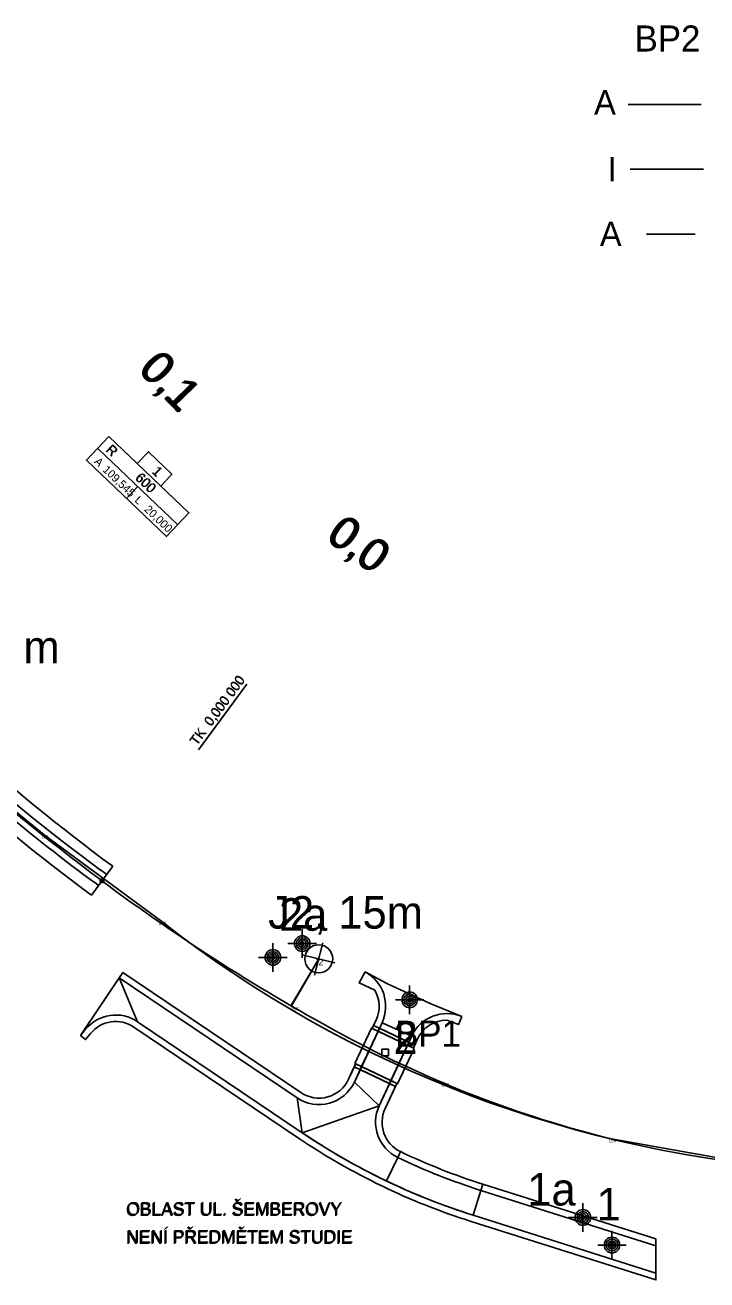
# Model space of a CAD drawing. Extents: x -606444 to -604546, y -1158114 to -1156869.
# Drawn here: x -604958.2 to -604748.6, y -1157651 to -1157265.4 of the extents above; entities that cross this region are included whole.
import ezdxf

# ---------------------------------------------------------------- set-up
doc = ezdxf.new("R2010")
doc.units = 0
for name, color, linetype in [('0_sondy', 7, 'Continuous'), ('B_CHOD', 7, 'Continuous'), ('B_TRAM', 7, 'Continuous'), ('B_VOZ', 7, 'Continuous'), ('jádrové vrty_předběžný GTP', 7, 'Continuous'), ('korozní průzkum', 7, 'Continuous'), ('legenda', 7, 'Continuous'), ('netisk', 7, 'Continuous'), ('netisk2', 7, 'Continuous'), ('NS_VB', 7, 'Continuous'), ('NS_VB_POP', 7, 'Continuous'), ('OSA', 7, 'Continuous'), ('OSAPOP', 7, 'Continuous'), ('podélný profil trasou tramvaje', 7, 'Continuous'), ('Sondy 2', 7, 'Continuous'), ('sondy současného průzkumu', 7, 'Continuous')]:
    doc.layers.add(name, color=color, linetype=linetype)

# ---------------------------------------------------------------- blocks, each defined once
blk = doc.blocks.new('709')
for p, q in [((0, 2.2), (0, -2.2)), ((-2.2, 0), (2.2, 0))]:
    blk.add_line(p, q)
for radius in [1.2, 0.9, 0.6, 0.3]:
    blk.add_circle((0, 0), radius)
blk = doc.blocks.new('IG vrt podr')
at = {"layer": 'sondy současného průzkumu'}
for p, q in [((0.41, 1.65), (-0.42, -1.67)), ((-1.7, 0.42), (1.64, -0.41))]:
    blk.add_line(p, q, dxfattribs=at)
blk.add_circle((0, 0), 1.43, dxfattribs=at)

msp = doc.modelspace()

# ---------------------------------------------------------------- linework, layer by layer
for p, q in [((-604952.36, -1157514.24), (-604952.46, -1157514.14)), ((-604952.36, -1157514.24), (-604952.46, -1157514.34)), ((-604952.36, -1157514.24), (-604952.26, -1157514.14)), ((-604952.36, -1157514.24), (-604952.26, -1157514.34)), ((-604916.22, -1157540.87), (-604916.32, -1157540.77)), ((-604916.22, -1157540.87), (-604916.32, -1157540.97)), ((-604916.22, -1157540.87), (-604916.12, -1157540.77)), ((-604916.22, -1157540.87), (-604916.12, -1157540.97)), ((-604867.95, -1157552.31), (-604868.05, -1157552.21)), ((-604867.95, -1157552.31), (-604868.05, -1157552.41)), ((-604867.95, -1157552.31), (-604867.85, -1157552.21)), ((-604867.95, -1157552.31), (-604867.85, -1157552.41)), ((-604875.6, -1157567.24), (-604875.7, -1157567.14)), ((-604875.6, -1157567.24), (-604875.7, -1157567.34)), ((-604875.6, -1157567.24), (-604875.5, -1157567.14)), ((-604875.6, -1157567.24), (-604875.5, -1157567.34)), ((-604829.38, -1157590.46), (-604829.48, -1157590.36)), ((-604829.38, -1157590.46), (-604829.48, -1157590.56)), ((-604829.38, -1157590.46), (-604829.28, -1157590.36)), ((-604829.38, -1157590.46), (-604829.28, -1157590.56)), ((-604777.97, -1157607.68), (-604778.07, -1157607.58)), ((-604777.97, -1157607.68), (-604778.07, -1157607.78)), ((-604777.97, -1157607.68), (-604777.87, -1157607.58)), ((-604777.97, -1157607.68), (-604777.87, -1157607.78))]:
    msp.add_line(p, q)
at = {"layer": 'B_CHOD'}
for p, q in [((-604818.1, -1157623.48), (-604817.49, -1157621.57)), ((-604818.1, -1157623.48), (-604817.49, -1157621.57)), ((-604817.49, -1157621.57), (-604764.31, -1157638.39)), ((-604817.49, -1157621.57), (-604764.31, -1157638.39)), ((-604764.31, -1157640.49), (-604818.1, -1157623.48)), ((-604764.31, -1157640.49), (-604818.1, -1157623.48)), ((-604764.31, -1157638.39), (-604764.31, -1157640.49)), ((-604764.31, -1157638.39), (-604764.31, -1157640.49))]:
    msp.add_line(p, q, dxfattribs=at)
for points in [[(-604873.47, -1157593.4), (-604928.14, -1157556.52), (-604929.26, -1157558.18), (-604874.59, -1157595.05)], [(-604873.47, -1157593.4), (-604928.14, -1157556.52), (-604929.26, -1157558.18), (-604874.59, -1157595.05)], [(-604853.73, -1157556.29), (-604855.56, -1157559.72), (-604850.68, -1157561.94)], [(-604853.73, -1157556.29), (-604855.56, -1157559.72), (-604850.68, -1157561.94)], [(-604873.06, -1157605.73), (-604923.64, -1157571.62)], [(-604873.06, -1157605.73), (-604923.64, -1157571.62)], [(-604851.11, -1157572.8), (-604851.53, -1157573.7), (-604849.72, -1157574.56), (-604849.3, -1157573.66), (-604851.11, -1157572.8)], [(-604851.11, -1157572.8), (-604851.53, -1157573.7), (-604849.72, -1157574.56), (-604849.3, -1157573.66), (-604851.11, -1157572.8)], [(-604850.31, -1157571.1), (-604851.11, -1157572.8), (-604849.3, -1157573.66), (-604848.5, -1157571.95)], [(-604850.31, -1157571.1), (-604851.11, -1157572.8), (-604849.3, -1157573.66), (-604848.5, -1157571.95)], [(-604828.56, -1157571.11), (-604825.03, -1157572.52), (-604824.01, -1157569.98)], [(-604828.56, -1157571.11), (-604825.03, -1157572.52), (-604824.01, -1157569.98)], [(-604939.63, -1157573.96), (-604941.17, -1157575.84), (-604939.62, -1157577.11), (-604938.08, -1157575.23)], [(-604939.63, -1157573.96), (-604941.17, -1157575.84), (-604939.62, -1157577.11), (-604938.08, -1157575.23)], [(-604924.76, -1157573.28), (-604874.18, -1157607.39)], [(-604924.76, -1157573.28), (-604874.18, -1157607.39)], [(-604856.82, -1157584.47), (-604856.6, -1157584.58), (-604854.79, -1157585.44), (-604849.72, -1157574.56), (-604851.53, -1157573.7), (-604851.75, -1157573.6), (-604856.82, -1157584.47)], [(-604856.82, -1157584.47), (-604856.6, -1157584.58), (-604854.79, -1157585.44), (-604849.72, -1157574.56), (-604851.53, -1157573.7), (-604851.75, -1157573.6), (-604856.82, -1157584.47)], [(-604839.38, -1157576.04), (-604840.26, -1157577.94), (-604838.45, -1157578.8), (-604837.56, -1157576.88)], [(-604839.38, -1157576.04), (-604840.26, -1157577.94), (-604838.45, -1157578.8), (-604837.56, -1157576.88)], [(-604838.65, -1157579.81), (-604838.88, -1157579.7), (-604840.68, -1157578.85), (-604845.76, -1157589.72), (-604843.95, -1157590.58), (-604843.72, -1157590.69), (-604838.65, -1157579.81)], [(-604838.65, -1157579.81), (-604838.88, -1157579.7), (-604840.68, -1157578.85), (-604845.76, -1157589.72), (-604843.95, -1157590.58), (-604843.72, -1157590.69), (-604838.65, -1157579.81)], [(-604838.88, -1157579.7), (-604838.45, -1157578.8), (-604840.26, -1157577.94), (-604840.68, -1157578.85), (-604838.88, -1157579.7)], [(-604838.88, -1157579.7), (-604838.45, -1157578.8), (-604840.26, -1157577.94), (-604840.68, -1157578.85), (-604838.88, -1157579.7)], [(-604856.6, -1157584.58), (-604857.02, -1157585.49), (-604855.21, -1157586.34), (-604854.79, -1157585.44), (-604856.6, -1157584.58)], [(-604856.6, -1157584.58), (-604857.02, -1157585.49), (-604855.21, -1157586.34), (-604854.79, -1157585.44), (-604856.6, -1157584.58)], [(-604857, -1157590.18), (-604855.21, -1157586.34), (-604857.02, -1157585.49), (-604858.81, -1157589.33)], [(-604857, -1157590.18), (-604855.21, -1157586.34), (-604857.02, -1157585.49), (-604858.81, -1157589.33)], [(-604847.56, -1157598.32), (-604844.37, -1157591.49), (-604846.18, -1157590.63), (-604849.37, -1157597.47)], [(-604847.56, -1157598.32), (-604844.37, -1157591.49), (-604846.18, -1157590.63), (-604849.37, -1157597.47)], [(-604844.37, -1157591.49), (-604843.95, -1157590.58), (-604845.76, -1157589.72), (-604846.18, -1157590.63), (-604844.37, -1157591.49)], [(-604844.37, -1157591.49), (-604843.95, -1157590.58), (-604845.76, -1157589.72), (-604846.18, -1157590.63), (-604844.37, -1157591.49)], [(-604843.68, -1157613.36), (-604843.68, -1157613.36), (-604842.81, -1157611.56)], [(-604842.81, -1157611.56), (-604842.81, -1157611.56), (-604843.68, -1157613.36)], [(-604843.68, -1157613.36), (-604843.68, -1157613.36), (-604842.81, -1157611.56)], [(-604842.81, -1157611.56), (-604842.81, -1157611.56), (-604843.68, -1157613.36)], [(-604818.1, -1157623.48), (-604817.49, -1157621.57)], [(-604818.1, -1157623.48), (-604817.49, -1157621.57)], [(-604821.11, -1157633.01), (-604764.31, -1157650.98), (-604764.31, -1157648.88), (-604820.51, -1157631.11)], [(-604821.11, -1157633.01), (-604764.31, -1157650.98), (-604764.31, -1157648.88), (-604820.51, -1157631.11)]]:
    msp.add_lwpolyline(points, dxfattribs=at)
for centre, radius, start, end in [((-604859.38, -1157566.88), 12, 335.0043, 61.9243), ((-604859.38, -1157566.88), 12, 335.0043, 61.9243), ((-604859.38, -1157566.88), 10, 335.0043, 29.5887), ((-604859.38, -1157566.88), 10, 335.0043, 29.5887), ((-604828.5, -1157581.11), 12, 68.0258, 155.0043), ((-604828.5, -1157581.11), 12, 68.0258, 155.0043), ((-604930.35, -1157581.57), 12, 56.0043, 140.6259), ((-604930.35, -1157581.57), 12, 56.0043, 140.6259), ((-604930.35, -1157581.57), 10, 56.0043, 140.6259), ((-604930.35, -1157581.57), 10, 56.0043, 140.6259), ((-604828.5, -1157581.11), 10, 90.366, 155.0043), ((-604828.5, -1157581.11), 10, 90.366, 155.0043), ((-604867.88, -1157585.11), 12, 236.0043, 335.0043), ((-604867.88, -1157585.11), 12, 236.0043, 335.0043), ((-604867.88, -1157585.11), 10, 236.0043, 335.0043), ((-604867.88, -1157585.11), 10, 236.0043, 335.0043), ((-604838.49, -1157602.54), 12, 155.0043, 244.4037), ((-604838.49, -1157602.54), 12, 155.0043, 244.4037), ((-604838.49, -1157602.54), 10, 155.0043, 244.404), ((-604838.49, -1157602.54), 10, 155.0043, 244.404), ((-604759, -1157436.6), 206, 236.0043, 252.4517), ((-604759, -1157436.6), 206, 236.0043, 252.4517), ((-604759, -1157436.6), 204, 236.0043, 252.4517), ((-604759, -1157436.6), 204, 236.0043, 252.4517), ((-604759, -1157436.6), 194, 244.404, 252.4516), ((-604759, -1157436.6), 194, 244.404, 252.4516), ((-604759, -1157436.6), 196, 244.404, 252.4516), ((-604759, -1157436.6), 196, 244.404, 252.4516)]:
    msp.add_arc(centre, radius, start, end, dxfattribs=at)
at = {"layer": 'B_TRAM'}
msp.add_line((-604937.81, -1157532.72), (-604931.28, -1157523.87), dxfattribs=at)
for radius in [594.5, 605.5]:
    msp.add_arc((-604578.51, -1157045.35), radius, 222.04255, 233.60158, dxfattribs=at)
at = {"layer": 'B_VOZ'}
for p, q in [((-604929.26, -1157558.18), (-604941.17, -1157575.84)), ((-604929.26, -1157558.18), (-604941.17, -1157575.84)), ((-604923.64, -1157571.62), (-604929.26, -1157558.18)), ((-604923.64, -1157571.62), (-604929.26, -1157558.18)), ((-604941.17, -1157575.84), (-604939.63, -1157573.96)), ((-604941.17, -1157575.84), (-604939.63, -1157573.96))]:
    msp.add_line(p, q, dxfattribs=at)
for points in [[(-604824.01, -1157569.98), (-604833.75, -1157566.05), (-604847.07, -1157559.84), (-604853.73, -1157556.29)], [(-604824.01, -1157569.98), (-604833.75, -1157566.05), (-604847.07, -1157559.84), (-604853.73, -1157556.29)], [(-604923.64, -1157571.62), (-604873.06, -1157605.73), (-604874.59, -1157595.05), (-604929.26, -1157558.18), (-604923.64, -1157571.62)], [(-604923.64, -1157571.62), (-604873.06, -1157605.73), (-604874.59, -1157595.05), (-604929.26, -1157558.18), (-604923.64, -1157571.62)], [(-604840.26, -1157577.94), (-604839.38, -1157576.04), (-604848.5, -1157571.95), (-604849.3, -1157573.66), (-604840.26, -1157577.94)], [(-604840.26, -1157577.94), (-604839.38, -1157576.04), (-604848.5, -1157571.95), (-604849.3, -1157573.66), (-604840.26, -1157577.94)], [(-604848.5, -1157571.95), (-604839.38, -1157576.04)], [(-604848.5, -1157571.95), (-604839.38, -1157576.04)], [(-604845.76, -1157589.72), (-604840.68, -1157578.85), (-604849.72, -1157574.56), (-604854.79, -1157585.44), (-604845.76, -1157589.72)], [(-604845.76, -1157589.72), (-604840.68, -1157578.85), (-604849.72, -1157574.56), (-604854.79, -1157585.44), (-604845.76, -1157589.72)], [(-604840.68, -1157578.85), (-604840.26, -1157577.94), (-604849.3, -1157573.66), (-604849.72, -1157574.56), (-604840.68, -1157578.85)], [(-604840.68, -1157578.85), (-604840.26, -1157577.94), (-604849.3, -1157573.66), (-604849.72, -1157574.56), (-604840.68, -1157578.85)], [(-604849.37, -1157597.47), (-604846.18, -1157590.63), (-604855.21, -1157586.34), (-604857, -1157590.18), (-604849.37, -1157597.47)], [(-604849.37, -1157597.47), (-604846.18, -1157590.63), (-604855.21, -1157586.34), (-604857, -1157590.18), (-604849.37, -1157597.47)], [(-604846.18, -1157590.63), (-604845.76, -1157589.72), (-604854.79, -1157585.44), (-604855.21, -1157586.34), (-604846.18, -1157590.63)], [(-604846.18, -1157590.63), (-604845.76, -1157589.72), (-604854.79, -1157585.44), (-604855.21, -1157586.34), (-604846.18, -1157590.63)], [(-604874.59, -1157595.05), (-604873.06, -1157605.73), (-604849.37, -1157597.47), (-604857, -1157590.18)], [(-604874.59, -1157595.05), (-604873.06, -1157605.73), (-604849.37, -1157597.47), (-604857, -1157590.18)], [(-604849.37, -1157597.47), (-604873.06, -1157605.73)], [(-604849.37, -1157597.47), (-604873.06, -1157605.73)], [(-604847.13, -1157620.58), (-604843.68, -1157613.36)], [(-604843.68, -1157613.36), (-604843.68, -1157613.36), (-604847.13, -1157620.58)], [(-604847.13, -1157620.58), (-604843.68, -1157613.36)], [(-604843.68, -1157613.36), (-604843.68, -1157613.36), (-604847.13, -1157620.58)], [(-604820.51, -1157631.11), (-604818.1, -1157623.48)], [(-604764.31, -1157640.49), (-604818.1, -1157623.48), (-604820.51, -1157631.11), (-604764.31, -1157648.88), (-604764.31, -1157640.49)], [(-604820.51, -1157631.11), (-604818.1, -1157623.48)], [(-604764.31, -1157640.49), (-604818.1, -1157623.48), (-604820.51, -1157631.11), (-604764.31, -1157648.88), (-604764.31, -1157640.49)]]:
    msp.add_lwpolyline(points, dxfattribs=at)
for centre, radius, start, end in [((-604859.38, -1157566.88), 12, 335.0043, 61.9245), ((-604859.38, -1157566.88), 12, 335.0043, 61.9245), ((-604828.5, -1157581.11), 12, 68.0258, 155.0043), ((-604828.5, -1157581.11), 12, 68.0258, 155.0043), ((-604930.35, -1157581.57), 12, 56.0043, 140.6259), ((-604930.35, -1157581.57), 12, 56.0043, 140.6259), ((-604867.88, -1157585.11), 12, 236.0043, 335.0043), ((-604867.88, -1157585.11), 12, 236.0043, 335.0043), ((-604838.49, -1157602.54), 12, 155.0043, 244.404), ((-604838.49, -1157602.54), 12, 155.0043, 244.404), ((-604759, -1157436.6), 204, 236.0043, 244.404), ((-604759, -1157436.6), 204, 236.0043, 244.404), ((-604759, -1157436.6), 196, 244.404, 252.4517), ((-604759, -1157436.6), 196, 244.404, 252.4517), ((-604759, -1157436.6), 204, 244.404, 252.4517), ((-604759, -1157436.6), 204, 244.404, 252.4517)]:
    msp.add_arc(centre, radius, start, end, dxfattribs=at)
at = {"layer": 'korozní průzkum'}
msp.add_lwpolyline([(-604848.6, -1157580.06), (-604846.52, -1157580.06), (-604846.52, -1157582.1), (-604848.6, -1157582.1)], close=True, dxfattribs=at)
at = {"layer": 'legenda'}
for p, q in [((-604772.89, -1157289.8), (-604750.39, -1157289.8)), ((-604772.22, -1157309.61), (-604749.72, -1157309.61))]:
    msp.add_line(p, q, dxfattribs=at)
at = {"layer": 'netisk'}
msp.add_line((-604876.35, -1157566.48), (-604867.95, -1157552.31), dxfattribs=at)
at = {"layer": 'netisk2'}
msp.add_line((-604867.95, -1157552.31), (-604876.34, -1157566.79), dxfattribs=at)
at = {"layer": 'NS_VB'}
for p, q in [((-604931.28, -1157523.87), (-604937.81, -1157532.72)), ((-604941.17, -1157575.84), (-604928.14, -1157556.52)), ((-604873.47, -1157593.4), (-604928.14, -1157556.52)), ((-604853.73, -1157556.29), (-604855.56, -1157559.72)), ((-604847.07, -1157559.84), (-604853.73, -1157556.29)), ((-604874.59, -1157595.05), (-604929.26, -1157558.18)), ((-604850.68, -1157561.94), (-604855.56, -1157559.72)), ((-604833.75, -1157566.05), (-604847.07, -1157559.84)), ((-604824.01, -1157569.98), (-604833.75, -1157566.05)), ((-604873.06, -1157605.73), (-604923.64, -1157571.62)), ((-604848.5, -1157571.95), (-604857, -1157590.18)), ((-604850.31, -1157571.1), (-604851.53, -1157573.7)), ((-604838.45, -1157578.8), (-604851.11, -1157572.8)), ((-604828.56, -1157571.11), (-604825.03, -1157572.52)), ((-604825.03, -1157572.52), (-604824.01, -1157569.98)), ((-604939.63, -1157573.96), (-604941.17, -1157575.84)), ((-604941.17, -1157575.84), (-604939.62, -1157577.11)), ((-604938.08, -1157575.23), (-604939.62, -1157577.11)), ((-604874.18, -1157607.39), (-604924.76, -1157573.28)), ((-604851.75, -1157573.6), (-604856.82, -1157584.47)), ((-604838.65, -1157579.81), (-604851.75, -1157573.6)), ((-604851.53, -1157573.7), (-604851.75, -1157573.6)), ((-604839.38, -1157576.04), (-604849.37, -1157597.47)), ((-604837.56, -1157576.88), (-604838.88, -1157579.7)), ((-604838.65, -1157579.81), (-604843.72, -1157590.69)), ((-604838.88, -1157579.7), (-604838.65, -1157579.81)), ((-604856.6, -1157584.58), (-604858.81, -1157589.33)), ((-604843.72, -1157590.69), (-604856.82, -1157584.47)), ((-604856.6, -1157584.58), (-604856.82, -1157584.47)), ((-604844.37, -1157591.49), (-604857.02, -1157585.49)), ((-604843.95, -1157590.58), (-604847.56, -1157598.32)), ((-604843.72, -1157590.69), (-604843.95, -1157590.58)), ((-604817.49, -1157621.57), (-604764.31, -1157638.39)), ((-604817.49, -1157621.57), (-604764.31, -1157638.39)), ((-604818.1, -1157623.48), (-604764.31, -1157640.49)), ((-604821.11, -1157633.01), (-604764.31, -1157650.98)), ((-604820.51, -1157631.11), (-604764.31, -1157648.88)), ((-604764.31, -1157638.39), (-604764.31, -1157650.98))]:
    msp.add_line(p, q, dxfattribs=at)
for points in [[(-604931.28, -1157523.87), (-604931.28, -1157523.87)], [(-604937.81, -1157532.72), (-604937.81, -1157532.72)]]:
    msp.add_lwpolyline(points, dxfattribs=at)
for centre, radius, start, end in [((-604578.51, -1157045.35), 594.5, 222.04255, 233.60156), ((-604578.51, -1157045.35), 605.5, 222.04255, 233.60156), ((-604859.38, -1157566.88), 12, 335.0043, 61.9247), ((-604859.38, -1157566.88), 10, 335.0043, 29.5887), ((-604828.5, -1157581.11), 12, 68.0258, 155.0043), ((-604930.35, -1157581.57), 12, 56.0043, 140.6259), ((-604930.35, -1157581.57), 10, 56.0043, 140.6259), ((-604828.5, -1157581.11), 10, 90.366, 155.0043), ((-604867.88, -1157585.11), 12, 236.0043, 335.0043), ((-604867.88, -1157585.11), 10, 236.0043, 335.0043), ((-604838.49, -1157602.54), 12, 155.0043, 244.404), ((-604838.49, -1157602.54), 10, 155.0043, 244.404), ((-604759, -1157436.6), 206, 236.0043, 252.4517), ((-604759, -1157436.6), 204, 236.0043, 252.4517), ((-604759, -1157436.6), 194, 244.404, 252.4517), ((-604759, -1157436.6), 196, 244.404, 252.4517)]:
    msp.add_arc(centre, radius, start, end, dxfattribs=at)
at = {"layer": 'OSA'}
for p, q in [((-604935.73, -1157529.9), (-604935.73, -1157529.9)), ((-604934.55, -1157528.29), (-604934.55, -1157528.29))]:
    msp.add_line(p, q, dxfattribs=at)
for points in [[(-604933.14, -1157526.39), (-604935.03, -1157525)], [(-604936.41, -1157529.19), (-604935.63, -1157529.76)], [(-604715.01, -1157617.16), (-604732.59, -1157615.76), (-604777.97, -1157607.65)]]:
    msp.add_lwpolyline(points, dxfattribs=at)
for centre, radius, start, end in [((-604578.51, -1157045.35), 600, 221.02098, 233.60156), ((-604591.87, -1157057.41), 580, 222.06105, 233.72643), ((-604593.66, -1157061.3), 580, 226.47692, 233.7757), ((-604575.5, -1157047.66), 600, 233.23961, 241.77802), ((-604693.72, -1157267.94), 350, 241.778, 256.0712)]:
    msp.add_arc(centre, radius, start, end, dxfattribs=at)
at = {"layer": 'OSAPOP'}
for p, q in [((-604932.45, -1157391.82), (-604923.76, -1157400.1)), ((-604911.29, -1157418.9), (-604935.9, -1157395.44)), ((-604939.35, -1157399.06), (-604914.74, -1157422.52)), ((-604923.76, -1157400.1), (-604916.53, -1157407)), ((-604923.59, -1157407.17), (-604927.05, -1157410.79)), ((-604916.53, -1157407), (-604907.84, -1157415.29)), ((-604904.88, -1157488.05), (-604890.04, -1157467.93)), ((-604935.14, -1157529.1), (-604933.95, -1157527.49)), ((-604935.14, -1157529.1), (-604933.95, -1157527.49))]:
    msp.add_line(p, q, dxfattribs=at)
msp.add_lwpolyline([(-604932.45, -1157391.82), (-604907.84, -1157415.29), (-604914.74, -1157422.52), (-604939.35, -1157399.06)], close=True, dxfattribs=at)
msp.add_lwpolyline([(-604923.76, -1157400.1), (-604920.31, -1157396.48), (-604913.07, -1157403.39), (-604916.53, -1157407)], dxfattribs=at)
msp.add_circle((-604934.55, -1157528.29), 0.6, dxfattribs=at)
msp.add_circle((-604934.55, -1157528.29), 0.6, dxfattribs=at)
at = {"layer": 'podélný profil trasou tramvaje'}
msp.add_line((-604767.23, -1157329.6), (-604752.23, -1157329.6), dxfattribs=at)
msp.add_lwpolyline([(-604973.89, -1157496.65), (-604952.36, -1157514.24), (-604916.22, -1157540.87)], dxfattribs=at)
msp.add_arc((-604692.61, -1157254.61), 363.25, 232.0059, 266.4651, dxfattribs=at)

# ---------------------------------------------------------------- block references
at = {"layer": '0_sondy', "xscale": 2, "yscale": 2}
for p in [(-604882.04, -1157551.88), (-604882.04, -1157551.88), (-604840.01, -1157564.91), (-604777.82, -1157640.26)]:
    msp.add_blockref('709', p, dxfattribs=at)
at = {"layer": 'jádrové vrty_předběžný GTP', "xscale": 3, "yscale": 3}
msp.add_blockref('IG vrt podr', (-604867.95, -1157552.31), dxfattribs=at)
at = {"layer": 'Sondy 2', "xscale": 2, "yscale": 2}
for p in [(-604873.02, -1157547.61), (-604786.77, -1157631.79)]:
    msp.add_blockref('709', p, dxfattribs=at)

# ---------------------------------------------------------------- texts
for s, height, p in [('155', 1, (-604953.26, -1157515.24)), ('156', 1, (-604917.15, -1157541.87)), ('J2', 2, (-604869.35, -1157554.31)), ('157', 1, (-604876.5, -1157568.24)), ('158', 1, (-604830.28, -1157591.46)), ('159', 1, (-604778.87, -1157608.68))]:
    msp.add_text(s, height=height).set_placement(p)
at = {"layer": '0_sondy'}
for s, p in [('2', (-604845, -1157581.54)), ('1', (-604782.56, -1157632.69))]:
    msp.add_text(s, height=10, dxfattribs=at).set_placement(p)
at = {"layer": 'jádrové vrty_předběžný GTP'}
for s, p in [('J3, 8 m', (-604991.45, -1157461.46)), ('J2, 15m', (-604883.5, -1157543.02))]:
    msp.add_text(s, height=10, dxfattribs=at).set_placement(p)
at = {"layer": 'korozní průzkum'}
for s, p in [('BP2', (-604770.86, -1157273.47)), ('BP1', (-604844.49, -1157579.3))]:
    msp.add_text(s, height=8, dxfattribs=at).set_placement(p)
at = {"layer": 'legenda'}
for s, p in [('A', (-604783.32, -1157292.83)), ('I', (-604779.13, -1157313.36))]:
    msp.add_text(s, height=7.5, dxfattribs=at).set_placement(p)
at = {"layer": 'NS_VB_POP'}
for s, p in [('OBLAST UL. ŠEMBEROVY', (-604927.25, -1157631.34)), ('OBLAST UL. ŠEMBEROVY', (-604927.1, -1157631.19)), ('OBLAST UL. ŠEMBEROVY', (-604926.95, -1157631.04)), ('NENÍ PŘEDMĚTEM STUDIE', (-604927.25, -1157639.91)), ('NENÍ PŘEDMĚTEM STUDIE', (-604927.1, -1157639.76)), ('NENÍ PŘEDMĚTEM STUDIE', (-604926.95, -1157639.61))]:
    msp.add_text(s, height=4, dxfattribs=at).set_placement(p)
at = {"layer": 'OSAPOP'}
for s, height, rotation, p in [('0,1', 10, 314.0523, (-604923.95, -1157371.43)), ('0,1', 10, 314.0523, (-604923.74, -1157371.43)), ('0,1', 10, 314.0523, (-604923.53, -1157371.44)), ('0,1', 10, 314.0523, (-604923.31, -1157371.44)), ('R', 3, 316.3563, (-604933.69, -1157396.16)), ('R', 3, 316.3563, (-604933.48, -1157396.16)), ('A', 2.5, 316.3563, (-604937.19, -1157399.74)), ('109,545', 2.5, 316.3563, (-604934.55, -1157402.25)), ('600', 3, 316.3563, (-604924.67, -1157404.77)), ('600', 3, 316.3563, (-604924.45, -1157404.76)), ('1', 3, 316.3563, (-604919.49, -1157402.8)), ('1', 3, 316.3563, (-604919.28, -1157402.79)), ('L', 2.5, 316.3563, (-604924.76, -1157411.58)), ('20,000', 2.5, 316.3563, (-604921.77, -1157414.44)), ('0,0', 10, 323.6016, (-604866.28, -1157423.33)), ('0,0', 10, 323.6016, (-604866.07, -1157423.3)), ('0,0', 10, 323.6016, (-604865.86, -1157423.27)), ('0,0', 10, 323.6016, (-604865.65, -1157423.23)), ('TK  0,000 000', 3, 53.6016, (-604905.42, -1157486.84)), ('TK  0,000 000', 3, 53.6016, (-604905.39, -1157487.05))]:
    msp.add_text(s, height=height, rotation=rotation, dxfattribs=at).set_placement(p)
at = {"layer": 'podélný profil trasou tramvaje'}
msp.add_text('A', height=7.5, dxfattribs=at).set_placement((-604781.54, -1157333.25))
at = {"layer": 'Sondy 2'}
for s, p in [('2a', (-604880.17, -1157543.67)), ('1a', (-604803.85, -1157628.12))]:
    msp.add_text(s, height=10, dxfattribs=at).set_placement(p)

doc.saveas('drawing.dxf')
